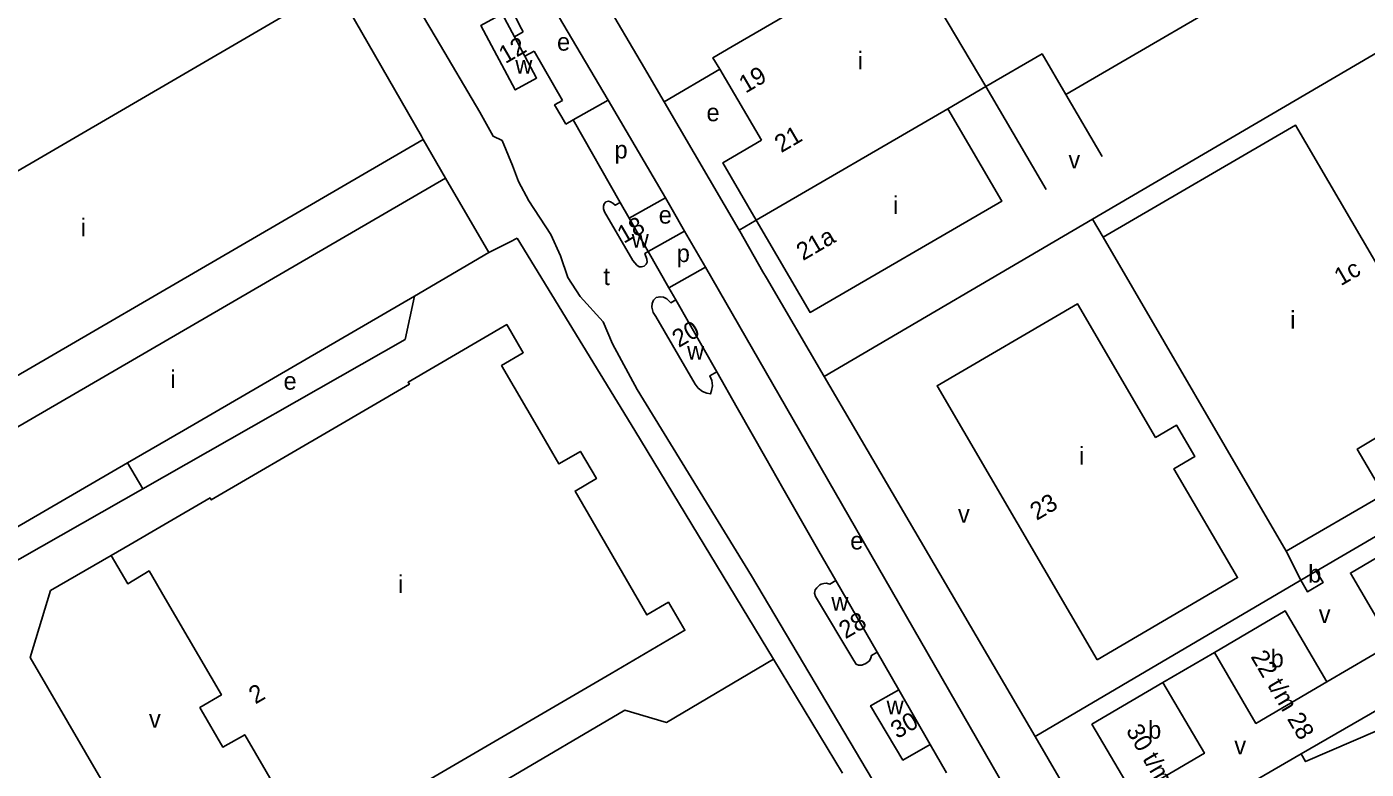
# Model space of a CAD drawing. Extents: x 157699 to 159683, y 381451 to 383293.
# Drawn here: x 159121.6 to 159425.3, y 382356.5 to 382524.8 of the extents above; entities that cross this region are included whole.
import ezdxf

# ---------------------------------------------------------------- set-up
doc = ezdxf.new("R2010")
doc.units = 0
for name, color, linetype in [('BLT_Basislijn', 7, 'Continuous'), ('BLT_Bebouwing', 7, 'Continuous'), ('BLT_Centroide', 7, 'Continuous'), ('BLT_Huisnummer', 7, 'Continuous'), ('BLT_Huisnummer_reeks', 7, 'Continuous'), ('BLT_Onderverdeling_panden', 7, 'Continuous')]:
    doc.layers.add(name, color=color, linetype=linetype)

msp = doc.modelspace()

# ---------------------------------------------------------------- linework, layer by layer
at = {"layer": 'BLT_Basislijn'}
for p, q in [((159232.2, 382522.57), (159234.17, 382523.68)), ((159435.12, 382523.3), (159363.3, 382481.22)), ((159234.56, 382518.16), (159236.65, 382519.33)), ((159278.72, 382515.21), (159266.16, 382507.83)), ((159245.52, 382503.74), (159253.41, 382508.18)), ((159283.14, 382478.73), (159266.16, 382507.83)), ((159357.21, 382509.45), (159365.45, 382495.4)), ((159243.8, 382502.77), (159245.52, 382503.74)), ((159211.48, 382499.28), (159216.55, 382490.54)), ((159258.23, 382481.41), (159266.43, 382486.02)), ((159287.03, 382480.97), (159283.14, 382478.73)), ((159365.67, 382477.11), (159363.3, 382481.22)), ((159262.52, 382473.88), (159270.78, 382478.52)), ((159231.08, 382476.02), (159226.39, 382473.62)), ((159232.78, 382476.88), (159231.08, 382476.02)), ((159267.22, 382465.62), (159275.51, 382470.3)), ((159260.02, 382442.6), (159285.94, 382400.36)), ((159147.89, 382420.05), (159144.4, 382425.95)), ((159293.07, 382420.21), (159301.24, 382405.94)), ((159301.24, 382405.94), (159305.09, 382399.25)), ((159407.2, 382405.92), (159410.49, 382399.37)), ((159491.41, 382406.79), (159410.57, 382359.98)), ((159285.94, 382400.36), (159334.86, 382317.96)), ((159305.09, 382399.25), (159314.4, 382383.04)), ((159410.49, 382399.37), (159350.24, 382363.95)), ((159416.41, 382376.33), (159431.15, 382384.96)), ((159314.4, 382383.04), (159319.32, 382374.49)), ((159390.91, 382382.94), (159379.22, 382376.15)), ((159319.32, 382374.49), (159326.45, 382362.08)), ((159326.45, 382362.08), (159330.13, 382355.66)), ((159361.69, 382344.41), (159350.24, 382363.95)), ((159410.57, 382359.98), (159391.6, 382348.99))]:
    msp.add_line(p, q, dxfattribs=at)
for points in [[(159191.38, 382561.09), (159194.21, 382557.16), (159197.6, 382551.33), (159205.57, 382537.24), (159214.43, 382522.22), (159224.32, 382505.48)], [(159253.41, 382508.18), (159237.02, 382536.04)], [(159229.98, 382531.95), (159233.78, 382524.37), (159234.17, 382523.68)], [(159261.68, 382515.44), (159252.23, 382531.57), (159251.98, 382531.9)], [(159232.2, 382522.57), (159229.41, 382527.8), (159224.57, 382525.15), (159232.37, 382510.53), (159237.21, 382513.18), (159234.56, 382518.16)], [(159234.56, 382518.16), (159232.2, 382522.57)], [(159236.65, 382519.33), (159243.05, 382508.09)], [(159261.68, 382515.44), (159262.22, 382514.53), (159266.16, 382507.83)], [(159339.1, 382511.27), (159352.76, 382487.96)], [(159242.91, 382504.3), (159241.29, 382507.1), (159243.05, 382508.09)], [(159266.43, 382486.02), (159253.41, 382508.18)], [(159224.32, 382505.48), (159227.39, 382500), (159229.39, 382499.04), (159231.76, 382493.4), (159233.08, 382489.76), (159235.41, 382485.33), (159240.46, 382477.77), (159242.65, 382472.86), (159244.3, 382468.02), (159247.09, 382463.69), (159252.29, 382457.94), (159254.39, 382452.98), (159260.02, 382442.6)], [(159243.8, 382502.77), (159242.91, 382504.3)], [(159245.52, 382503.74), (159256.19, 382485)], [(159256.19, 382485), (159255.05, 382484.35), (159254.51, 382484.85), (159254, 382485.12), (159253.48, 382485.26), (159252.91, 382485.11), (159252.51, 382484.68), (159252.38, 382484.16), (159252.38, 382483.57), (159252.57, 382482.86), (159259.04, 382471.82), (159259.94, 382470.77), (159260.49, 382470.4), (159260.99, 382470.4), (159261.6, 382470.59), (159262.06, 382471.04), (159262.29, 382471.48), (159262.23, 382472.14), (159261.72, 382473.42), (159262.52, 382473.88)], [(159256.19, 382485), (159258.23, 382481.41)], [(159270.78, 382478.52), (159267.98, 382483.38), (159266.43, 382486.02)], [(159258.23, 382481.41), (159262.52, 382473.88)], [(159363.3, 382481.22), (159302.41, 382445.54)], [(159275.51, 382470.3), (159270.78, 382478.52)], [(159288.53, 382469.26), (159283.29, 382478.47), (159283.14, 382478.73)], [(159232.78, 382476.88), (159259.49, 382433.33), (159290.9, 382381.46)], [(159232.78, 382476.88), (159259.49, 382433.33), (159290.9, 382381.46)], [(159262.52, 382473.88), (159267.22, 382465.62)], [(159351.7, 382337.93), (159296.79, 382433.33), (159275.51, 382470.3)], [(159302.41, 382445.54), (159289.31, 382467.88), (159288.53, 382469.26)], [(159267.22, 382465.62), (159268.76, 382462.92)], [(159147.89, 382420.05), (159207.41, 382453.95), (159209.49, 382463.79)], [(159268.76, 382462.92), (159267.61, 382462.26), (159266.73, 382463.18), (159265.96, 382463.55), (159265.2, 382463.63), (159264.34, 382463.46), (159263.74, 382462.81), (159263.41, 382462.12), (159263.33, 382461.27), (159263.66, 382460.04), (159264.27, 382459.11), (159273.15, 382443.82), (159273.84, 382442.93), (159274.82, 382442.11), (159275.8, 382441.79), (159276.61, 382441.58), (159276.86, 382442.38), (159277.09, 382443.39), (159276.91, 382444.65), (159276.5, 382445.71), (159278.05, 382446.59)], [(159268.76, 382462.92), (159278.05, 382446.59)], [(159278.05, 382446.59), (159282.7, 382438.43)], [(159350.24, 382363.95), (159309.56, 382433.33), (159302.41, 382445.54)], [(159282.7, 382438.43), (159289.2, 382427)], [(159475.99, 382437.6), (159414.02, 382401.4)], [(159289.2, 382427), (159293.07, 382420.21)], [(159103.9, 382364.71), (159106.84, 382366.39), (159115.66, 382401.7), (159147.89, 382420.05)], [(159175.76, 382344.81), (159152.01, 382330.98), (159122.37, 382381.82), (159126.95, 382397), (159140.75, 382404.94)], [(159410.57, 382359.98), (159411.58, 382358.24), (159433.32, 382367.59), (159457.14, 382382.69), (159481.58, 382397.01), (159487.75, 382400.41), (159489.13, 382401.27), (159490.41, 382402.52), (159491.35, 382403.99), (159491.93, 382405.55)], [(159305.09, 382399.25), (159303.71, 382398.46), (159302.95, 382398.7), (159302.37, 382398.63), (159301.77, 382398.43), (159301.47, 382398.29), (159301.19, 382398.09), (159300.73, 382397.66), (159300.38, 382397.2), (159300.22, 382396.42), (159300.45, 382395.68), (159309.14, 382381.11), (159309.68, 382380.3), (159310.23, 382380.1), (159310.97, 382380.06), (159311.9, 382380.45), (159312.7, 382381.08), (159313.03, 382381.74), (159313.12, 382382.31), (159314.4, 382383.04)], [(159180.52, 382282.77), (159159.85, 382318.49), (159166.7, 382322.45), (159173.96, 382320.88), (159257.22, 382369.88), (159266.66, 382367.11), (159290.9, 382381.46)], [(159290.9, 382381.46), (159306.55, 382355.63)], [(159319.32, 382374.49), (159312.95, 382370.87), (159320.27, 382358.57), (159326.45, 382362.08)]]:
    msp.add_lwpolyline(points, dxfattribs=at)
at = {"layer": 'BLT_Bebouwing'}
for p, q in [((159288.18, 382499.1), (159278.72, 382515.21)), ((159339.1, 382511.27), (159330.43, 382506.26)), ((159365.67, 382477.11), (159407.2, 382405.92)), ((159226.39, 382473.62), (159209.49, 382463.79)), ((159144.4, 382425.95), (159091.79, 382395.35)), ((159410.49, 382399.37), (159414.02, 382401.4)), ((159199.93, 382346.62), (159254.08, 382378.19))]:
    msp.add_line(p, q, dxfattribs=at)
for points in [[(159423.24, 382542.01), (159408.67, 382532.99), (159405.86, 382537.84), (159357.21, 382509.45)], [(159191.55, 382534.13), (159211.08, 382500.02), (159211.48, 382499.28)], [(159278.72, 382515.21), (159277.2, 382517.82), (159281.52, 382520.34), (159303.35, 382533.07)], [(159357.21, 382509.45), (159351.84, 382518.67), (159339.1, 382511.27)], [(159287.03, 382480.97), (159299.22, 382460.06), (159342.7, 382485.26), (159330.43, 382506.26)], [(159407.2, 382405.92), (159429.35, 382418.76), (159423.32, 382429.1), (159444.77, 382441.93), (159409.29, 382502.56), (159365.67, 382477.11)], [(159211.48, 382499.28), (159076.33, 382420.7)], [(159288.18, 382499.1), (159279.43, 382493.98), (159287.03, 382480.97)], [(159081.93, 382412.26), (159216.55, 382490.54)], [(159216.55, 382490.54), (159226.39, 382473.62)], [(159209.49, 382463.79), (159157.1, 382433.33), (159144.4, 382425.95)], [(159152.69, 382411.91), (159163.17, 382418.02), (159163.43, 382417.57), (159190.42, 382433.33), (159208.35, 382443.81), (159208.08, 382444.23), (159230.44, 382457.3), (159234.17, 382450.94), (159229.28, 382448.03), (159237.83, 382433.33), (159242.26, 382425.72), (159247.16, 382428.56), (159250.77, 382422.39), (159245.94, 382419.56), (159262.21, 382391.49), (159267.11, 382394.36), (159270.84, 382388.01), (159254.08, 382378.19)], [(159140.75, 382404.94), (159145.07, 382407.46), (159152.69, 382411.91)], [(159437.82, 382410.4), (159421.75, 382400.96), (159431.15, 382384.96)], [(159152.96, 382395.22), (159149.33, 382401.44), (159144.48, 382398.55), (159140.75, 382404.94)], [(159414.02, 382401.4), (159415.55, 382398.81), (159412, 382396.75), (159410.49, 382399.37)], [(159152.96, 382395.22), (159165.74, 382373.35), (159160.84, 382370.49), (159161.13, 382369.99)], [(159416.41, 382376.33), (159406.98, 382392.38), (159390.91, 382382.94)], [(159390.91, 382382.94), (159400.34, 382366.89), (159416.41, 382376.33)], [(159379.22, 382376.15), (159363.14, 382366.71), (159372.57, 382350.66)], [(159372.57, 382350.66), (159388.64, 382360.1), (159379.22, 382376.15)], [(159161.13, 382369.99), (159166.04, 382361.53), (159171.04, 382364.31), (159180.7, 382347.7), (159175.76, 382344.81)]]:
    msp.add_lwpolyline(points, dxfattribs=at)
msp.add_lwpolyline([(159364.29, 382381.33), (159328.02, 382443.45), (159359.86, 382462.04), (159377.56, 382431.74), (159382.29, 382434.54), (159386.47, 382427.38), (159381.72, 382424.61), (159396.15, 382399.93)], close=True, dxfattribs=at)
at = {"layer": 'BLT_Onderverdeling_panden'}
for p, q in [((159320.28, 382542.95), (159339.1, 382511.27)), ((159107.07, 382484.9), (159191.55, 382534.13)), ((159287.03, 382480.97), (159330.43, 382506.26))]:
    msp.add_line(p, q, dxfattribs=at)

# ---------------------------------------------------------------- texts
at = {"layer": 'BLT_Centroide'}
for s, p in [('e', (159241.84, 382519.42)), ('w', (159232.38, 382514.22)), ('i', (159310.02, 382515.17)), ('e', (159275.74, 382503.41)), ('p', (159254.88, 382494.97)), ('v', (159357.81, 382492.72)), ('i', (159318.06, 382482.41)), ('e', (159264.9, 382480.2)), ('i', (159133.84, 382477.34)), ('w', (159258.78, 382474.74)), ('p', (159268.99, 382471.48)), ('t', (159252.35, 382466.26)), ('i', (159408.11, 382456.4)), ('w', (159271.33, 382449.38)), ('i', (159154.16, 382442.94)), ('e', (159179.82, 382442.55)), ('i', (159360.2, 382425.58)), ('v', (159332.76, 382412.39)), ('e', (159308.33, 382406.33)), ('b', (159412.18, 382398.83)), ('i', (159205.77, 382396.47)), ('w', (159304.06, 382392.44)), ('v', (159414.58, 382389.68)), ('b', (159403.66, 382379.62)), ('w', (159316.58, 382368.95)), ('v', (159149.3, 382365.92)), ('b', (159375.89, 382363.41)), ('v', (159395.43, 382359.89))]:
    msp.add_text(s, height=4, dxfattribs=at).set_placement(p)
at = {"layer": 'BLT_Huisnummer'}
for s, rotation, p in [('12', 30.1314, (159230.12, 382516.35)), ('18', 30.1314, (159256.98, 382475.59)), ('21a', 30.3013, (159297.61, 382471.69)), ('1c', 30.3013, (159419.57, 382465.98)), ('20', 30.1314, (159269.43, 382451.99)), ('23', 30.3013, (159350.6, 382412.8)), ('28', 30.1314, (159307.25, 382385.94)), ('2', 30.1765, (159173.43, 382371.15)), ('30', 30.1314, (159318.99, 382363.28))]:
    msp.add_text(s, height=4, rotation=rotation, dxfattribs=at).set_placement(p)
at = {"layer": 'BLT_Huisnummer_reeks'}
for s, rotation, p in [('19', 30.3013, (159284.59, 382509.66)), ('21', 30.3013, (159292.67, 382496.16)), ('22 t/m 28', 300.4018, (159399.03, 382382.03)), ('30 t/m 34', 300.4264, (159370.74, 382365.28))]:
    msp.add_text(s, height=4, rotation=rotation, dxfattribs=at).set_placement(p)

doc.saveas('drawing.dxf')
